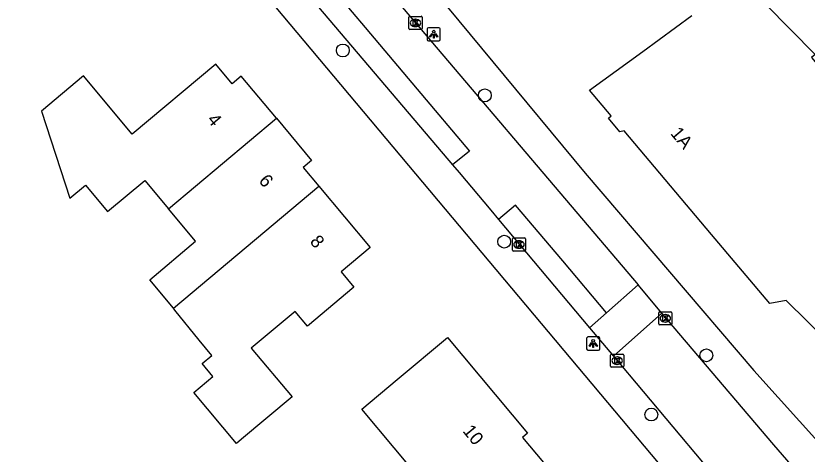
# Model space of a CAD drawing. Extents: x 161772 to 163123, y 383092 to 383917.
# Drawn here: x 162013.5 to 162073.6, y 383407.6 to 383440.9 of the extents above; entities that cross this region are included whole.
import ezdxf

# ---------------------------------------------------------------- set-up
doc = ezdxf.new("R2010")
doc.units = 0
for name, color, linetype in [('IMGEO_Boom', 7, 'Continuous'), ('IMGEO_Kolk', 7, 'Continuous'), ('IMGEO_Lichtpunt', 7, 'Continuous'), ('IMGEO_Pand', 7, 'Continuous'), ('IMGEO_Pand_nummerreeks', 7, 'Continuous'), ('IMGEO_Rijbaan_lokaal_open', 7, 'Continuous'), ('IMGEO_Voetpad_gesloten', 7, 'Continuous')]:
    doc.layers.add(name, color=color, linetype=linetype)

msp = doc.modelspace()

# ---------------------------------------------------------------- linework, layer by layer
at = {"layer": 'IMGEO_Boom'}
for centre in [(162038.32, 383438.275), (162049.106, 383434.863), (162050.58, 383423.769), (162065.935, 383415.144), (162061.751, 383410.652)]:
    msp.add_circle(centre, 0.489, dxfattribs=at)
at = {"layer": 'IMGEO_Kolk'}
for p, q in [((162043.335, 383439.938), (162043.335, 383440.79)), ((162043.41, 383440.864), (162044.262, 383440.864)), ((162044.336, 383440.79), (162044.336, 383439.938)), ((162043.846, 383440.084), (162043.821, 383440.084)), ((162043.823, 383440.644), (162043.848, 383440.644)), ((162044.262, 383439.864), (162043.41, 383439.864)), ((162051.199, 383423.124), (162051.199, 383423.976)), ((162051.274, 383424.05), (162052.126, 383424.05)), ((162051.687, 383423.83), (162051.712, 383423.83)), ((162052.2, 383423.976), (162052.2, 383423.124)), ((162051.71, 383423.27), (162051.685, 383423.27)), ((162052.126, 383423.05), (162051.274, 383423.05)), ((162062.39, 383418.453), (162063.242, 383418.453)), ((162062.315, 383417.527), (162062.315, 383418.379)), ((162062.803, 383418.233), (162062.828, 383418.233)), ((162063.316, 383418.379), (162063.316, 383417.527)), ((162063.242, 383417.453), (162062.39, 383417.453)), ((162062.826, 383417.673), (162062.801, 383417.673)), ((162058.66, 383414.314), (162058.66, 383415.166)), ((162058.735, 383415.24), (162059.587, 383415.24)), ((162059.148, 383415.02), (162059.173, 383415.02)), ((162059.661, 383415.166), (162059.661, 383414.314)), ((162059.587, 383414.24), (162058.735, 383414.24)), ((162059.171, 383414.46), (162059.146, 383414.46))]:
    msp.add_line(p, q, dxfattribs=at)
for points in [[(162043.335, 383439.938), (162043.335, 383440.79)], [(162043.41, 383440.864), (162044.262, 383440.864)], [(162044.336, 383440.79), (162044.336, 383439.938)], [(162043.656, 383440.564), (162043.779, 383440.564), (162043.779, 383440.413), (162043.909, 383440.564), (162044.073, 383440.564), (162043.927, 383440.413), (162044.08, 383440.164), (162043.928, 383440.164), (162043.843, 383440.328), (162043.779, 383440.261), (162043.779, 383440.164), (162043.656, 383440.164), (162043.656, 383440.564)], [(162044.262, 383439.864), (162043.41, 383439.864)], [(162051.199, 383423.124), (162051.199, 383423.976)], [(162051.274, 383424.05), (162052.126, 383424.05)], [(162052.2, 383423.976), (162052.2, 383423.124)], [(162051.52, 383423.75), (162051.643, 383423.75), (162051.643, 383423.599), (162051.773, 383423.75), (162051.937, 383423.75), (162051.791, 383423.599), (162051.944, 383423.35), (162051.792, 383423.35), (162051.707, 383423.514), (162051.643, 383423.447), (162051.643, 383423.35), (162051.52, 383423.35), (162051.52, 383423.75)], [(162052.126, 383423.05), (162051.274, 383423.05)], [(162062.39, 383418.453), (162063.242, 383418.453)], [(162062.315, 383417.527), (162062.315, 383418.379)], [(162062.636, 383418.153), (162062.759, 383418.153), (162062.759, 383418.002), (162062.889, 383418.153), (162063.053, 383418.153), (162062.907, 383418.002), (162063.06, 383417.753), (162062.908, 383417.753), (162062.823, 383417.917), (162062.759, 383417.85), (162062.759, 383417.753), (162062.636, 383417.753), (162062.636, 383418.153)], [(162063.316, 383418.379), (162063.316, 383417.527)], [(162063.242, 383417.453), (162062.39, 383417.453)], [(162058.66, 383414.314), (162058.66, 383415.166)], [(162058.735, 383415.24), (162059.587, 383415.24)], [(162058.981, 383414.94), (162059.104, 383414.94), (162059.104, 383414.789), (162059.234, 383414.94), (162059.398, 383414.94), (162059.252, 383414.789), (162059.405, 383414.54), (162059.253, 383414.54), (162059.168, 383414.704), (162059.104, 383414.637), (162059.104, 383414.54), (162058.981, 383414.54), (162058.981, 383414.94)], [(162059.661, 383415.166), (162059.661, 383414.314)], [(162059.587, 383414.24), (162058.735, 383414.24)]]:
    msp.add_lwpolyline(points, dxfattribs=at)
for centre, start, end in [((162043.412, 383440.788), 91.55205, 178.44795), ((162043.412, 383440.788), 91.55205, 178.44795), ((162044.26, 383440.788), 1.55205, 88.44795), ((162044.26, 383440.788), 1.55205, 88.44795), ((162043.412, 383439.94), 181.55205, 268.44795), ((162043.412, 383439.94), 181.55205, 268.44795), ((162044.26, 383439.94), 271.55205, 358.44795), ((162044.26, 383439.94), 271.55205, 358.44795), ((162051.276, 383423.974), 91.55205, 178.44795), ((162051.276, 383423.974), 91.55205, 178.44795), ((162052.124, 383423.974), 1.55205, 88.44795), ((162052.124, 383423.974), 1.55205, 88.44795), ((162051.276, 383423.126), 181.55205, 268.44795), ((162051.276, 383423.126), 181.55205, 268.44795), ((162052.124, 383423.126), 271.55205, 358.44795), ((162052.124, 383423.126), 271.55205, 358.44795), ((162062.392, 383418.377), 91.55205, 178.44795), ((162062.392, 383418.377), 91.55205, 178.44795), ((162063.24, 383418.377), 1.55205, 88.44795), ((162063.24, 383418.377), 1.55205, 88.44795), ((162062.392, 383417.529), 181.55205, 268.44795), ((162062.392, 383417.529), 181.55205, 268.44795), ((162063.24, 383417.529), 271.55205, 358.44795), ((162063.24, 383417.529), 271.55205, 358.44795), ((162058.737, 383415.164), 91.55205, 178.44795), ((162058.737, 383415.164), 91.55205, 178.44795), ((162059.585, 383415.164), 1.55205, 88.44795), ((162059.585, 383415.164), 1.55205, 88.44795), ((162058.737, 383414.316), 181.55205, 268.44795), ((162058.737, 383414.316), 181.55205, 268.44795), ((162059.585, 383414.316), 271.55205, 358.44795), ((162059.585, 383414.316), 271.55205, 358.44795)]:
    msp.add_arc(centre, 0.0765, start, end, dxfattribs=at)
for centre, major_axis, ratio, start_param, end_param in [((162043.822, 383440.364), (-0.387, 0.002), 0.722429, 4.712389, 7.853982), ((162043.847, 383440.364), (-0.39, 0.002), 0.717154, 1.570796, 4.712389), ((162051.686, 383423.55), (-0.387, 0.002), 0.722429, 4.712389, 7.853982), ((162051.711, 383423.55), (-0.39, 0.002), 0.717154, 1.570796, 4.712389), ((162062.802, 383417.953), (-0.387, 0.002), 0.722429, 4.712389, 7.853982), ((162062.827, 383417.953), (-0.39, 0.002), 0.717154, 1.570796, 4.712389), ((162059.147, 383414.74), (-0.387, 0.002), 0.722429, 4.712389, 7.853982), ((162059.172, 383414.74), (-0.39, 0.002), 0.717154, 1.570796, 4.712389)]:
    msp.add_ellipse(centre, major_axis=major_axis, ratio=ratio, start_param=start_param, end_param=end_param, dxfattribs=at)
at = {"layer": 'IMGEO_Lichtpunt'}
for p, q in [((162044.722, 383439.906), (162044.722, 383439.099)), ((162044.722, 383439.906), (162044.722, 383439.099)), ((162045.624, 383440.001), (162044.816, 383440.001)), ((162045.624, 383440.001), (162044.816, 383440.001)), ((162045.718, 383439.099), (162045.718, 383439.906)), ((162045.718, 383439.099), (162045.718, 383439.906)), ((162044.816, 383439.005), (162045.624, 383439.005)), ((162044.816, 383439.005), (162045.624, 383439.005)), ((162056.843, 383416.443), (162056.843, 383415.636)), ((162056.843, 383416.443), (162056.843, 383415.636)), ((162057.745, 383416.538), (162056.937, 383416.538)), ((162057.745, 383416.538), (162056.937, 383416.538)), ((162057.839, 383415.636), (162057.839, 383416.443)), ((162057.839, 383415.636), (162057.839, 383416.443)), ((162056.937, 383415.542), (162057.745, 383415.542)), ((162056.937, 383415.542), (162057.745, 383415.542))]:
    msp.add_line(p, q, dxfattribs=at)
for points in [[(162045.096, 383439.57), (162045.135, 383439.542), (162044.947, 383439.28), (162044.909, 383439.307), (162045.096, 383439.57)], [(162045.198, 383439.522), (162045.245, 383439.522), (162045.245, 383439.2), (162045.198, 383439.2), (162045.198, 383439.522)], [(162045.308, 383439.542), (162045.346, 383439.569), (162045.533, 383439.307), (162045.494, 383439.279), (162045.308, 383439.542)], [(162057.217, 383416.107), (162057.256, 383416.079), (162057.068, 383415.817), (162057.03, 383415.844), (162057.217, 383416.107)], [(162057.319, 383416.059), (162057.366, 383416.059), (162057.366, 383415.737), (162057.319, 383415.737), (162057.319, 383416.059)], [(162057.429, 383416.079), (162057.467, 383416.106), (162057.654, 383415.844), (162057.615, 383415.816), (162057.429, 383416.079)]]:
    msp.add_lwpolyline(points, dxfattribs=at)
for centre in [(162045.221, 383439.704), (162057.342, 383416.241)]:
    msp.add_circle(centre, 0.0994, dxfattribs=at)
for centre, start, end in [((162044.816, 383439.906), 90, 180), ((162044.816, 383439.906), 90, 180), ((162045.624, 383439.906), 0, 90), ((162045.624, 383439.906), 0, 90), ((162044.816, 383439.099), 180, 270), ((162044.816, 383439.099), 180, 270), ((162045.624, 383439.099), 270, 0), ((162045.624, 383439.099), 270, 360), ((162056.937, 383416.443), 90, 180), ((162056.937, 383416.443), 90, 180), ((162057.745, 383416.443), 0, 90), ((162057.745, 383416.443), 0, 90), ((162056.937, 383415.636), 180, 270), ((162056.937, 383415.636), 180, 270), ((162057.745, 383415.636), 270, 0), ((162057.745, 383415.636), 270, 360)]:
    msp.add_arc(centre, 0.0946, start, end, dxfattribs=at)
at = {"layer": 'IMGEO_Pand'}
for points in [[(162068.574, 383443.678), (162074.214, 383437.973), (162073.937, 383437.739), (162076.155, 383435.117), (162077.315, 383436.099), (162080.197, 383437.293), (162085.051, 383431.555), (162083.042, 383428.917), (162077.548, 383424.268), (162080.35, 383420.398), (162079.091, 383419.333), (162075.274, 383416.103), (162072.008, 383419.306), (162070.761, 383419.081), (162066.336, 383424.31), (162059.684, 383432.171), (162059.37, 383432.114), (162058.505, 383433.136), (162058.708, 383433.308), (162057.059, 383435.257), (162061.102, 383438.199), (162064.838, 383440.938)], [(162033.275, 383433.128), (162030.599, 383436.321), (162029.911, 383435.745), (162028.664, 383437.233), (162022.319, 383431.917), (162018.614, 383436.338), (162015.416, 383433.658), (162017.568, 383427.062), (162018.761, 383428.061), (162020.444, 383426.053), (162023.264, 383428.416), (162025.074, 383426.256)], [(162025.074, 383426.256), (162033.275, 383433.128)], [(162033.275, 383433.128), (162035.949, 383429.937), (162035.309, 383429.401), (162036.507, 383427.971)], [(162036.507, 383427.971), (162040.4, 383423.326), (162038.19, 383421.475), (162039.161, 383420.316), (162035.626, 383417.353), (162034.688, 383418.473), (162031.364, 383415.688), (162034.459, 383411.995), (162030.628, 383408.784), (162030.231, 383408.451), (162026.988, 383412.322), (162028.445, 383413.543), (162027.628, 383414.518), (162028.369, 383415.139), (162027.404, 383416.291), (162025.567, 383418.583), (162025.456, 383418.715)], [(162025.456, 383418.715), (162036.507, 383427.971)], [(162025.456, 383418.715), (162023.645, 383420.877), (162027.133, 383423.799), (162025.074, 383426.256)], [(162042.442, 383413.304), (162046.279, 383416.509), (162052.35, 383409.242), (162051.959, 383408.915), (162054.742, 383405.585), (162050.598, 383402.122), (162051.674, 383400.885), (162050.321, 383399.709), (162052.378, 383397.343), (162047.321, 383392.948), (162046.001, 383394.468), (162040.357, 383389.564), (162031.415, 383399.854), (162035.794, 383403.659), (162038.856, 383400.136), (162044.666, 383405.185), (162039.757, 383411.061), (162042.442, 383413.304)]]:
    msp.add_lwpolyline(points, dxfattribs=at)
at = {"layer": 'IMGEO_Rijbaan_lokaal_open'}
for points in [[(162034.776, 383451.058), (162038.41, 383446.77), (162040.822, 383443.925), (162060.745, 383420.481)], [(162034.744, 383443.6), (162036.054, 383444.697), (162040.018, 383440.006), (162043.957, 383435.348), (162047.931, 383430.647), (162046.657, 383429.59)], [(162046.657, 383429.59), (162047.148, 383429.013), (162049.56, 383426.147), (162050.138, 383425.46)], [(162058.355, 383418.369), (162055.02, 383422.31), (162051.448, 383426.528), (162050.138, 383425.46)], [(162060.745, 383420.481), (162058.355, 383418.369)], [(162062.563, 383418.343), (162060.745, 383420.481)], [(162057.064, 383417.229), (162058.355, 383418.369)], [(162062.563, 383418.343), (162058.872, 383415.082)], [(162077.699, 383401.158), (162076.743, 383402.112), (162073.542, 383405.497), (162071.059, 383408.345), (162062.563, 383418.343)], [(162057.064, 383417.229), (162058.872, 383415.082)], [(162058.872, 383415.082), (162070.146, 383401.685)]]:
    msp.add_lwpolyline(points, dxfattribs=at)
at = {"layer": 'IMGEO_Voetpad_gesloten'}
for points in [[(162027.495, 383466.15), (162027.9, 383463.647), (162030.791, 383459.92), (162042.704, 383445.878), (162056.737, 383428.976), (162069.531, 383413.985), (162082.036, 383400.151), (162085.851, 383396.183), (162119.667, 383362.459), (162125.116, 383357.112)], [(162013.474, 383465.049), (162067.97, 383400.221)], [(162034.744, 383443.6), (162046.657, 383429.59)], [(162050.138, 383425.46), (162057.064, 383417.229)]]:
    msp.add_lwpolyline(points, dxfattribs=at)

# ---------------------------------------------------------------- texts
at = {"layer": 'IMGEO_Pand_nummerreeks'}
for s, rotation, p in [('4', 310.25733, (162027.956, 383432.993)), ('1A', 310.27872, (162063.159, 383431.956)), ('6', 310.25808, (162031.878, 383428.362)), ('8', 309.96656, (162035.765, 383423.75)), ('10', 309.40414, (162047.375, 383409.385))]:
    msp.add_text(s, height=1, rotation=rotation, dxfattribs=at).set_placement(p)

doc.saveas('drawing.dxf')
